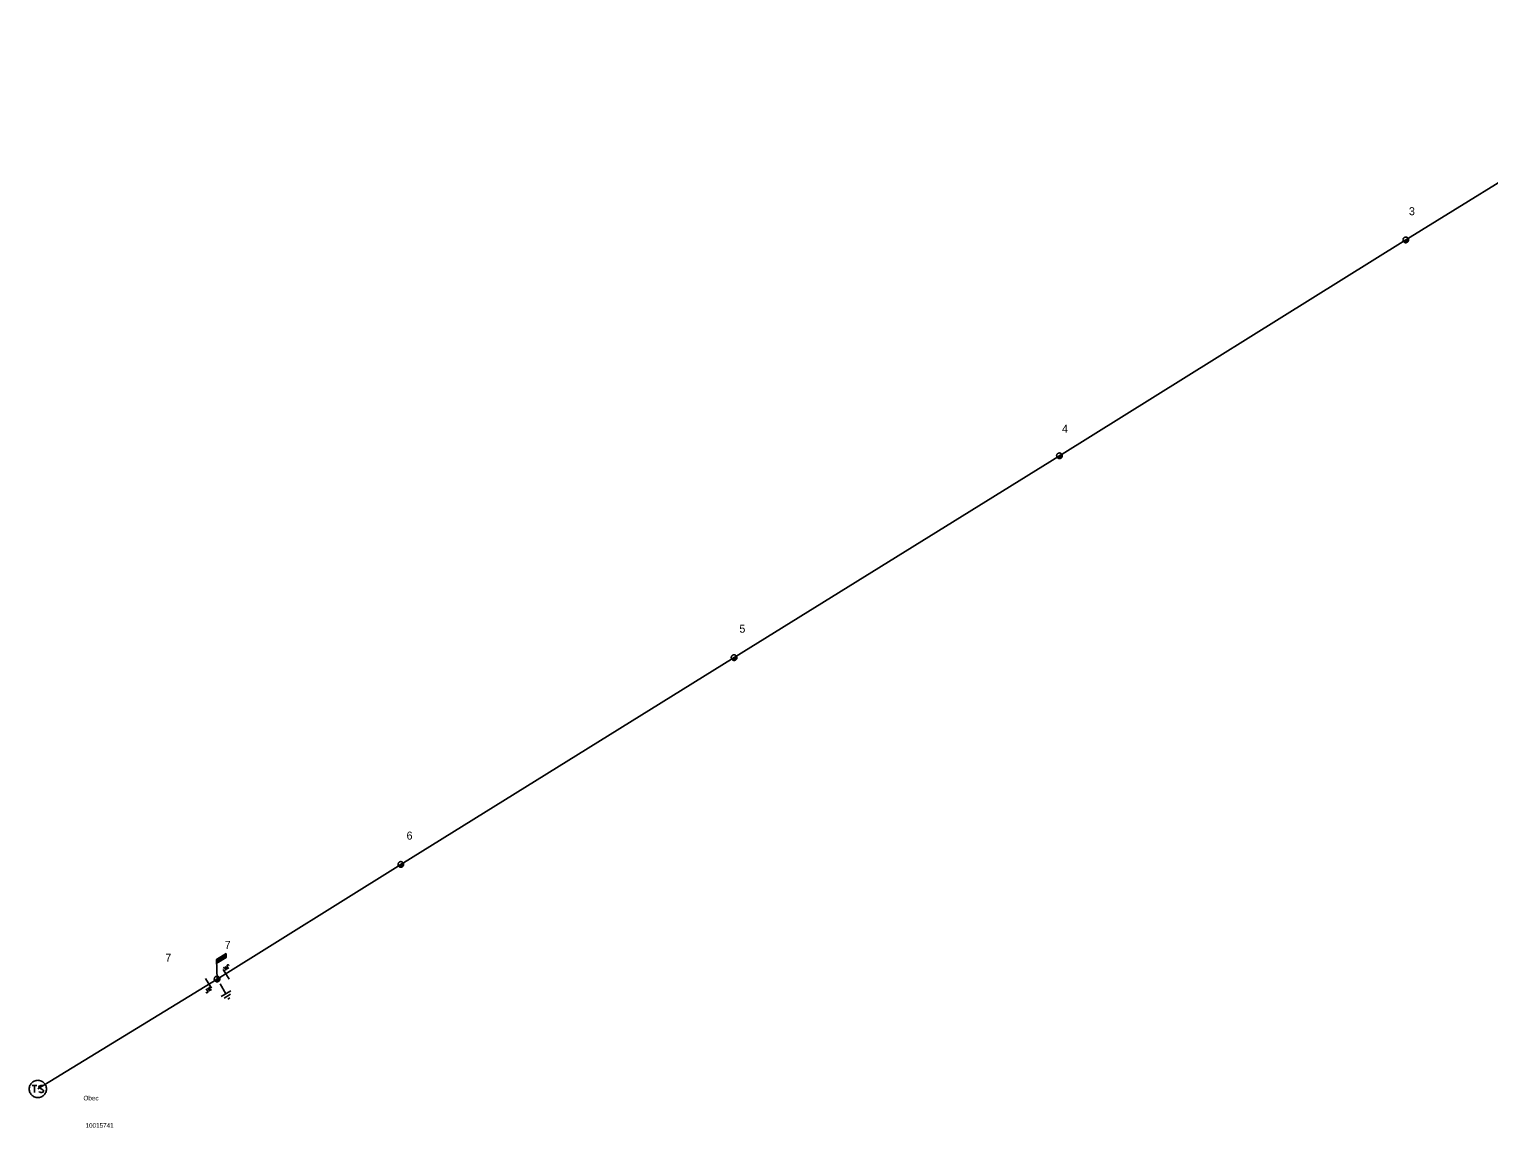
# Model space of a CAD drawing. Extents: x -788491 to -785797, y -1154753 to -1152002.
# Drawn here: x -787220.9 to -786901.8, y -1152780.4 to -1152540.3 of the extents above; entities that cross this region are included whole.
import ezdxf

# ---------------------------------------------------------------- set-up
doc = ezdxf.new("R2010")
doc.units = 0
for name, color, linetype in [('Default', 7, 'Continuous'), ('Vrstva 11', 7, 'Continuous'), ('Vrstva 12', 7, 'Continuous'), ('Vrstva 13', 7, 'Continuous'), ('Vrstva 14', 7, 'Continuous'), ('Vrstva 15', 7, 'Continuous'), ('Vrstva 18', 7, 'Continuous'), ('Vrstva 2', 7, 'Continuous'), ('Vrstva 25', 7, 'Continuous'), ('Vrstva 26', 7, 'Continuous'), ('Vrstva 27', 7, 'Continuous'), ('Vrstva 4', 7, 'Continuous'), ('Vrstva 6', 7, 'Continuous')]:
    doc.layers.add(name, color=color, linetype=linetype)

# ---------------------------------------------------------------- blocks, each defined once
blk = doc.blocks.new('VN840')
at = {"layer": 'Vrstva 15'}
for points in [[(-0.01, 1.41), (-0.01, -1.09)], [(-1.51, -1.24), (-1.51, -1.15)], [(-1.48, -1.35), (-1.51, -1.24)], [(-1.33, -1.42), (-1.48, -1.35)], [(-1.27, -1.42), (-1.33, -1.42)], [(-1.13, -1.35), (-1.27, -1.42)], [(-1.09, -1.24), (-1.13, -1.35)], [(-1.09, -0.59), (-1.09, -1.24)], [(-0.68, -0.59), (-0.68, -1.42)], [(-0.68, -1.11), (-0.27, -0.59)], [(-0.54, -0.94), (-0.2, -1.42)]]:
    blk.add_lwpolyline(points, dxfattribs=at)
blk = doc.blocks.new('VN440')
at = {"layer": 'Vrstva 2'}
for points in [[(1.22, 0), (1.21, 0.13), (1.19, 0.25), (1.16, 0.38), (1.11, 0.5), (1.05, 0.61), (0.98, 0.72), (0.9, 0.82), (0.81, 0.91), (0.71, 0.99), (0.6, 1.06), (0.49, 1.12), (0.37, 1.16), (0.25, 1.2), (0.12, 1.22), (-0.01, 1.22), (-0.14, 1.22), (-0.26, 1.2), (-0.39, 1.16), (-0.51, 1.12), (-0.62, 1.06), (-0.73, 0.99), (-0.83, 0.91), (-0.92, 0.82), (-1, 0.72), (-1.07, 0.61), (-1.13, 0.5), (-1.18, 0.38), (-1.21, 0.25), (-1.23, 0.13), (-1.24, 0), (-1.23, -0.13), (-1.21, -0.26), (-1.18, -0.38), (-1.13, -0.5), (-1.07, -0.62), (-1, -0.73), (-0.92, -0.83), (-0.83, -0.92), (-0.73, -1), (-0.62, -1.07), (-0.51, -1.13), (-0.39, -1.17), (-0.26, -1.2), (-0.14, -1.23), (-0.01, -1.23), (0.12, -1.23), (0.25, -1.2), (0.37, -1.17), (0.49, -1.13), (0.6, -1.07), (0.71, -1), (0.81, -0.92), (0.9, -0.83), (0.98, -0.73), (1.05, -0.62), (1.11, -0.5), (1.16, -0.38), (1.19, -0.26), (1.21, -0.13), (1.22, 0)], [(-1.24, 0), (1.22, 0)], [(-1.18, -0.34), (1.1, -0.34)], [(-1.01, -0.63), (0.97, -0.63)], [(-0.74, -0.92), (0.68, -0.92)]]:
    blk.add_lwpolyline(points, dxfattribs=at)
blk = doc.blocks.new('VN810')
at = {"layer": 'Vrstva 14'}
for points in [[(0, -1.25), (0, -3.75)], [(1.25, -3.75), (-1.25, -3.75)], [(0.77, -4.37), (-0.8, -4.37)], [(0, -5), (-0.25, -5)], [(0.27, -5), (0, -5)]]:
    blk.add_lwpolyline(points, dxfattribs=at)
blk = doc.blocks.new('VN610')
at = {"layer": 'Vrstva 6'}
for points in [[(1.88, 0), (1.87, 0.2), (1.84, 0.39), (1.79, 0.58), (1.72, 0.77), (1.63, 0.94), (1.52, 1.11), (1.4, 1.26), (1.26, 1.4), (1.1, 1.53), (0.94, 1.63), (0.76, 1.72), (0.58, 1.8), (0.39, 1.85), (0.19, 1.88), (-0.01, 1.89), (-0.21, 1.88), (-0.4, 1.85), (-0.59, 1.8), (-0.78, 1.72), (-0.95, 1.63), (-1.12, 1.53), (-1.27, 1.4), (-1.41, 1.26), (-1.54, 1.11), (-1.64, 0.94), (-1.73, 0.77), (-1.8, 0.58), (-1.86, 0.39), (-1.89, 0.2), (-1.9, 0), (-1.89, -0.2), (-1.86, -0.39), (-1.8, -0.58), (-1.73, -0.77), (-1.64, -0.95), (-1.54, -1.11), (-1.41, -1.27), (-1.27, -1.41), (-1.12, -1.53), (-0.95, -1.64), (-0.78, -1.73), (-0.59, -1.8), (-0.4, -1.85), (-0.21, -1.88), (-0.01, -1.89), (0.19, -1.88), (0.39, -1.85), (0.58, -1.8), (0.76, -1.73), (0.94, -1.64), (1.1, -1.53), (1.26, -1.41), (1.4, -1.27), (1.52, -1.11), (1.63, -0.95), (1.72, -0.77), (1.79, -0.58), (1.84, -0.39), (1.87, -0.2), (1.88, 0)], [(-1.27, 0.78), (-0.26, 0.78)], [(-0.76, 0.78), (-0.76, -0.79)], [(1.19, 0.66), (0.94, 0.78), (0.62, 0.78), (0.37, 0.66), (0.24, 0.47), (0.24, 0.4), (0.37, 0.22), (1.12, -0.16), (1.25, -0.32), (1.25, -0.48), (1.12, -0.67), (0.87, -0.79), (0.62, -0.79), (0.49, -0.73), (0.24, -0.6)]]:
    blk.add_lwpolyline(points, dxfattribs=at)
blk = doc.blocks.new('VN001')
at = {"layer": 'Default'}
for p, q in [((1.85, 3.23), (4.26, 3.23)), ((1.87, 3.28), (4.29, 3.28)), ((1.9, 3.33), (4.32, 3.33)), ((1.93, 3.38), (4.35, 3.38)), ((1.96, 3.43), (4.37, 3.43)), ((1.99, 3.48), (4.4, 3.48)), ((2.02, 3.53), (4.43, 3.53)), ((2.05, 3.58), (4.46, 3.58)), ((2.07, 3.63), (4.49, 3.63)), ((2.1, 3.68), (4.52, 3.68)), ((2.13, 3.73), (2.54, 3.73)), ((1.73, 3.03), (4.14, 3.03)), ((1.76, 3.08), (4.17, 3.08)), ((1.79, 3.13), (4.2, 3.13)), ((1.82, 3.18), (4.23, 3.18))]:
    blk.add_line(p, q, dxfattribs=at)
blk.add_lwpolyline([(2.13, 3.73), (0, 0)], dxfattribs=at)
blk.add_lwpolyline([(4.55, 3.73), (2.13, 3.73), (1.7, 2.98), (4.12, 2.99)], close=True, dxfattribs=at)

msp = doc.modelspace()

# ---------------------------------------------------------------- linework, layer by layer
at = {"layer": 'Vrstva 4'}
for points in [[(-786697.17, -1152540.35), (-786769.95, -1152542.46), (-786853.34, -1152545.31), (-786919.93, -1152586.38), (-786995.65, -1152633.55), (-787066.79, -1152677.65), (-787139.65, -1152722.84), (-787179.82, -1152747.88)], [(-787179.82, -1152747.88), (-787219.01, -1152771.91)]]:
    msp.add_lwpolyline(points, dxfattribs=at)

# ---------------------------------------------------------------- block references
at = {"layer": 'Vrstva 11', "rotation": 31.288813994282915}
msp.add_blockref('VN001', (-787179.82, -1152747.88), dxfattribs=at)
at = {"layer": 'Vrstva 13'}
for p, xscale, yscale, rotation in [((-786919.93, -1152586.38), 0.5000000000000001, 0.5000000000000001, 31.517372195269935), ((-786995.65, -1152633.55), 0.49999999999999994, 0.5, 31.722191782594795), ((-787066.79, -1152677.65), 0.49999999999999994, 0.5000000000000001, 31.38368607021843), ((-787139.65, -1152722.84), 0.5000000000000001, 0.4999999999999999, 32.31264166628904), ((-787179.82, -1152747.88), 0.5, 0.5, 31.409583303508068)]:
    msp.add_blockref('VN440', p, dxfattribs=dict(at, xscale=xscale, yscale=yscale, rotation=rotation))
at = {"layer": 'Vrstva 15', "rotation": 31.105491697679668}
msp.add_blockref('VN810', (-787179.82, -1152747.88), dxfattribs=at)
at = {"layer": 'Vrstva 18'}
for p, rotation in [((-787177.92, -1152746.7), -148.06223056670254), ((-787181.59, -1152748.97), 31.559822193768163)]:
    msp.add_blockref('VN840', p, dxfattribs=dict(at, rotation=rotation))
at = {"layer": 'Vrstva 25', "rotation": -0.018891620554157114}
msp.add_blockref('VN610', (-787219.01, -1152771.91), dxfattribs=at)

# ---------------------------------------------------------------- texts
at = {"layer": 'Vrstva 12'}
msp.add_text('7', height=1.75, dxfattribs=at).set_placement((-787191.15, -1152744.12))
at = {"layer": 'Vrstva 14'}
for s, p in [('3', (-786919.24, -1152580.99)), ('4', (-786995.11, -1152628.54)), ('5', (-787065.63, -1152672.21)), ('6', (-787138.4, -1152717.42)), ('7', (-787178.17, -1152741.31))]:
    msp.add_text(s, height=1.75, dxfattribs=at).set_placement(p)
at = {"layer": 'Vrstva 26'}
msp.add_text('10015741', height=1, dxfattribs=at).set_placement((-787208.59, -1152780.38))
at = {"layer": 'Vrstva 27'}
msp.add_text('Obec', height=1, dxfattribs=at).set_placement((-787209.04, -1152774.4))

doc.saveas('drawing.dxf')
